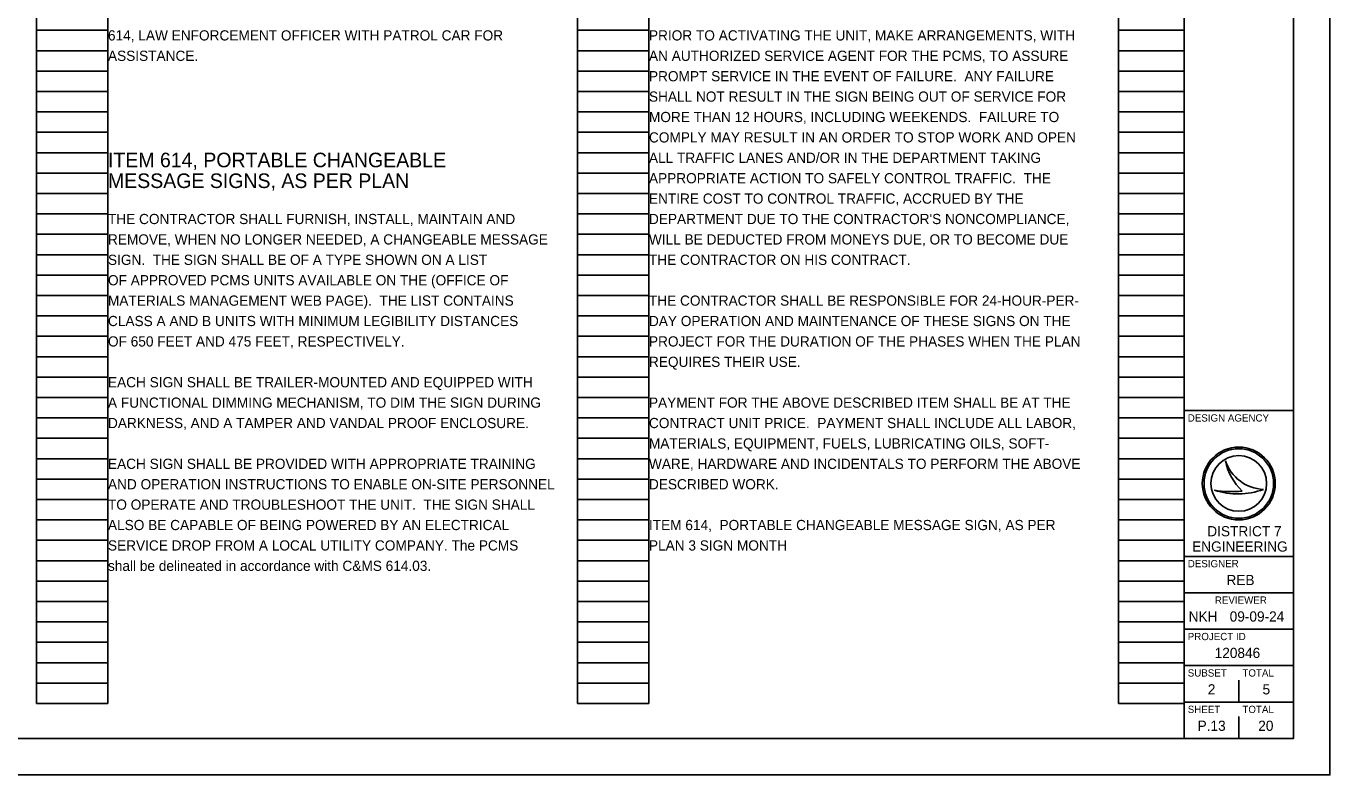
# Model space of a CAD drawing. Extents: x -7.9 to 34, y 0 to 22.
# Drawn here: x 16.12 to 34, y 0 to 10.28 of the extents above; entities that cross this region are included whole.
import ezdxf

# ---------------------------------------------------------------- set-up
doc = ezdxf.new("R2010")
doc.units = 0
for name, color, linetype in [('Default', 7, 'Continuous'), ('SH_Border', 7, 'Continuous'), ('SH_Cut_Line', 7, 'Continuous'), ('SH_Data', 7, 'Continuous'), ('SH_Text', 7, 'Continuous')]:
    doc.layers.add(name, color=color, linetype=linetype)

msp = doc.modelspace()

# ---------------------------------------------------------------- linework, layer by layer
at = {"layer": 'SH_Border'}
for p, q in [((32, 0.5), (32, 21.5)), ((32, 5), (33.5, 5)), ((32, 3), (33.5, 3)), ((32, 2.5), (33.5, 2.5)), ((32, 2), (33.5, 2)), ((32, 1.5), (33.5, 1.5)), ((32, 1), (33.5, 1))]:
    msp.add_line(p, q, dxfattribs=at)
msp.add_lwpolyline([(1.5, 21.5), (33.5, 21.5), (33.5, 0.5), (1.5, 0.5)], close=True, dxfattribs=at)
at = {"layer": 'SH_Cut_Line'}
msp.add_lwpolyline([(0, 0), (34, 0), (34, 22), (0, 22)], close=True, dxfattribs=at)
at = {"layer": 'SH_Data'}
for p, q in [((16.26, 0.98), (16.26, 21.14)), ((17.24, 0.98), (17.24, 21.14)), ((23.68, 0.98), (23.68, 21.14)), ((24.66, 0.98), (24.66, 21.14)), ((31.1, 0.98), (31.1, 21.14)), ((32, 0.98), (32, 21.14)), ((16.26, 10.22), (17.24, 10.22)), ((23.68, 10.22), (24.66, 10.22)), ((31.1, 10.22), (32, 10.22)), ((16.26, 9.94), (17.24, 9.94)), ((23.68, 9.94), (24.66, 9.94)), ((31.1, 9.94), (32, 9.94)), ((16.26, 9.66), (17.24, 9.66)), ((23.68, 9.66), (24.66, 9.66)), ((31.1, 9.66), (32, 9.66)), ((16.26, 9.38), (17.24, 9.38)), ((23.68, 9.38), (24.66, 9.38)), ((31.1, 9.38), (32, 9.38)), ((16.26, 9.1), (17.24, 9.1)), ((23.68, 9.1), (24.66, 9.1)), ((31.1, 9.1), (32, 9.1)), ((16.26, 8.82), (17.24, 8.82)), ((23.68, 8.82), (24.66, 8.82)), ((31.1, 8.82), (32, 8.82)), ((16.26, 8.54), (17.24, 8.54)), ((23.68, 8.54), (24.66, 8.54)), ((31.1, 8.54), (32, 8.54)), ((16.26, 8.26), (17.24, 8.26)), ((23.68, 8.26), (24.66, 8.26)), ((31.1, 8.26), (32, 8.26)), ((16.26, 7.98), (17.24, 7.98)), ((23.68, 7.98), (24.66, 7.98)), ((31.1, 7.98), (32, 7.98)), ((16.26, 7.7), (17.24, 7.7)), ((23.68, 7.7), (24.66, 7.7)), ((31.1, 7.7), (32, 7.7)), ((16.26, 7.42), (17.24, 7.42)), ((23.68, 7.42), (24.66, 7.42)), ((31.1, 7.42), (32, 7.42)), ((16.26, 7.14), (17.24, 7.14)), ((23.68, 7.14), (24.66, 7.14)), ((31.1, 7.14), (32, 7.14)), ((16.26, 6.86), (17.24, 6.86)), ((23.68, 6.86), (24.66, 6.86)), ((31.1, 6.86), (32, 6.86)), ((16.26, 6.58), (17.24, 6.58)), ((23.68, 6.58), (24.66, 6.58)), ((31.1, 6.58), (32, 6.58)), ((16.26, 6.3), (17.24, 6.3)), ((23.68, 6.3), (24.66, 6.3)), ((31.1, 6.3), (32, 6.3)), ((16.26, 6.02), (17.24, 6.02)), ((23.68, 6.02), (24.66, 6.02)), ((31.1, 6.02), (32, 6.02)), ((16.26, 5.74), (17.24, 5.74)), ((23.68, 5.74), (24.66, 5.74)), ((31.1, 5.74), (32, 5.74)), ((16.26, 5.46), (17.24, 5.46)), ((23.68, 5.46), (24.66, 5.46)), ((31.1, 5.46), (32, 5.46)), ((16.26, 5.18), (17.24, 5.18)), ((23.68, 5.18), (24.66, 5.18)), ((31.1, 5.18), (32, 5.18)), ((16.26, 4.9), (17.24, 4.9)), ((23.68, 4.9), (24.66, 4.9)), ((31.1, 4.9), (32, 4.9)), ((16.26, 4.62), (17.24, 4.62)), ((23.68, 4.62), (24.66, 4.62)), ((31.1, 4.62), (32, 4.62)), ((16.26, 4.34), (17.24, 4.34)), ((23.68, 4.34), (24.66, 4.34)), ((31.1, 4.34), (32, 4.34)), ((32.567, 4.31), (32.567, 4.31)), ((16.26, 4.06), (17.24, 4.06)), ((23.68, 4.06), (24.66, 4.06)), ((31.1, 4.06), (32, 4.06)), ((32.75, 4), (32.75, 4)), ((16.26, 3.78), (17.24, 3.78)), ((23.68, 3.78), (24.66, 3.78)), ((31.1, 3.78), (32, 3.78)), ((32.417, 3.91), (32.417, 3.91)), ((33.087, 3.919), (33.087, 3.919)), ((16.26, 3.5), (17.24, 3.5)), ((23.68, 3.5), (24.66, 3.5)), ((31.1, 3.5), (32, 3.5)), ((16.26, 3.22), (17.24, 3.22)), ((23.68, 3.22), (24.66, 3.22)), ((31.1, 3.22), (32, 3.22)), ((16.26, 2.94), (17.24, 2.94)), ((23.68, 2.94), (24.66, 2.94)), ((31.1, 2.94), (32, 2.94)), ((16.26, 2.66), (17.24, 2.66)), ((23.68, 2.66), (24.66, 2.66)), ((31.1, 2.66), (32, 2.66)), ((16.26, 2.38), (17.24, 2.38)), ((23.68, 2.38), (24.66, 2.38)), ((31.1, 2.38), (32, 2.38)), ((16.26, 2.1), (17.24, 2.1)), ((23.68, 2.1), (24.66, 2.1)), ((31.1, 2.1), (32, 2.1)), ((16.26, 1.82), (17.24, 1.82)), ((23.68, 1.82), (24.66, 1.82)), ((31.1, 1.82), (32, 1.82)), ((16.26, 1.54), (17.24, 1.54)), ((23.68, 1.54), (24.66, 1.54)), ((31.1, 1.54), (32, 1.54)), ((16.26, 1.26), (17.24, 1.26)), ((23.68, 1.26), (24.66, 1.26)), ((31.1, 1.26), (32, 1.26)), ((32.75, 1), (32.75, 1.3)), ((16.26, 0.98), (17.24, 0.98)), ((23.68, 0.98), (24.66, 0.98)), ((31.1, 0.98), (32, 0.98)), ((32.75, 0.5), (32.75, 0.8)), ((32.375, 0.675), (32.375, 0.675))]:
    msp.add_line(p, q, dxfattribs=at)
for radius in [0.5, 0.477, 0.477, 0.382]:
    msp.add_circle((32.75, 4), radius, dxfattribs=at)
for centre, radius, start, end in [((33.116, 4.498), 0.58, 198.9257, 198.9319), ((33.347, 4.47), 0.796, 191.6379, 191.6421), ((33.116, 4.498), 0.58, 198.9319, 267.1657), ((33.347, 4.47), 0.796, 191.6421, 226.0947), ((32.739, 4.87), 1.013, 251.4576, 290.0832), ((32.648, 5.154), 1.266, 259.4964, 259.4995), ((32.739, 4.87), 1.013, 251.4527, 251.4576), ((32.648, 5.154), 1.266, 259.4995, 276.6672)]:
    msp.add_arc(centre, radius, start, end, dxfattribs=at)

# ---------------------------------------------------------------- texts
at = {"layer": 'Default'}
for s, height, p in [('ITEM 614, PORTABLE CHANGEABLE ', 0.2, (17.24, 8.34)), ('MESSAGE SIGNS, AS PER PLAN', 0.2, (17.24, 8.055)), ('120846', 0.14, (32.419, 1.605))]:
    msp.add_text(s, height=height, dxfattribs=at).set_placement(p)
at = {"layer": 'SH_Data'}
for s, height, p in [('DESIGN AGENCY', 0.1, (32.05, 4.85)), ('DESIGNER', 0.1, (32.05, 2.85)), ('REB', 0.14, (32.581, 2.605)), ('REVIEWER', 0.1, (32.422, 2.35)), ('NKH', 0.14, (32.062, 2.105)), ('09-09-24', 0.14, (32.625, 2.105)), ('PROJECT ID', 0.1, (32.05, 1.85)), ('SUBSET', 0.1, (32.05, 1.35)), ('TOTAL', 0.1, (32.8, 1.35)), ('2', 0.14, (32.325, 1.105)), ('5', 0.14, (33.076, 1.105)), ('SHEET', 0.1, (32.05, 0.85)), ('TOTAL', 0.1, (32.8, 0.85)), ('P.13', 0.14, (32.185, 0.605)), ('20', 0.14, (33.017, 0.605))]:
    msp.add_text(s, height=height, dxfattribs=at).set_placement(p)
at = {"layer": 'SH_Text'}
for s, p in [('614, LAW ENFORCEMENT OFFICER WITH PATROL CAR FOR', (17.24, 10.08)), ('PRIOR TO ACTIVATING THE UNIT, MAKE ARRANGEMENTS, WITH ', (24.66, 10.08)), ('ASSISTANCE.', (17.24, 9.8)), ('AN AUTHORIZED SERVICE AGENT FOR THE PCMS, TO ASSURE', (24.66, 9.8)), ('PROMPT SERVICE IN THE EVENT OF FAILURE.  ANY FAILURE', (24.66, 9.52)), ('SHALL NOT RESULT IN THE SIGN BEING OUT OF SERVICE FOR', (24.66, 9.24)), ('MORE THAN 12 HOURS, INCLUDING WEEKENDS.  FAILURE TO', (24.66, 8.96)), ('COMPLY MAY RESULT IN AN ORDER TO STOP WORK AND OPEN', (24.66, 8.68)), ('ALL TRAFFIC LANES AND/OR IN THE DEPARTMENT TAKING', (24.66, 8.4)), ('APPROPRIATE ACTION TO SAFELY CONTROL TRAFFIC.  THE', (24.66, 8.12)), ('ENTIRE COST TO CONTROL TRAFFIC, ACCRUED BY THE', (24.66, 7.84)), ('THE CONTRACTOR SHALL FURNISH, INSTALL, MAINTAIN AND', (17.24, 7.56)), ("DEPARTMENT DUE TO THE CONTRACTOR'S NONCOMPLIANCE,", (24.66, 7.56)), ('REMOVE, WHEN NO LONGER NEEDED, A CHANGEABLE MESSAGE', (17.24, 7.28)), ('WILL BE DEDUCTED FROM MONEYS DUE, OR TO BECOME DUE', (24.66, 7.28)), ('SIGN.  THE SIGN SHALL BE OF A TYPE SHOWN ON A LIST', (17.24, 7)), ('THE CONTRACTOR ON HIS CONTRACT.', (24.66, 7)), ('OF APPROVED PCMS UNITS AVAILABLE ON THE (OFFICE OF', (17.24, 6.72)), ('MATERIALS MANAGEMENT WEB PAGE).  THE LIST CONTAINS', (17.24, 6.44)), ('THE CONTRACTOR SHALL BE RESPONSIBLE FOR 24-HOUR-PER-', (24.66, 6.44)), ('CLASS A AND B UNITS WITH MINIMUM LEGIBILITY DISTANCES', (17.24, 6.16)), ('DAY OPERATION AND MAINTENANCE OF THESE SIGNS ON THE', (24.66, 6.16)), ('OF 650 FEET AND 475 FEET, RESPECTIVELY.', (17.24, 5.88)), ('PROJECT FOR THE DURATION OF THE PHASES WHEN THE PLAN', (24.66, 5.88)), ('REQUIRES THEIR USE.', (24.66, 5.6)), ('EACH SIGN SHALL BE TRAILER-MOUNTED AND EQUIPPED WITH', (17.24, 5.32)), ('A FUNCTIONAL DIMMING MECHANISM, TO DIM THE SIGN DURING', (17.24, 5.04)), ('PAYMENT FOR THE ABOVE DESCRIBED ITEM SHALL BE AT THE', (24.66, 5.04)), ('DARKNESS, AND A TAMPER AND VANDAL PROOF ENCLOSURE.', (17.24, 4.76)), ('CONTRACT UNIT PRICE.  PAYMENT SHALL INCLUDE ALL LABOR,', (24.66, 4.76)), ('MATERIALS, EQUIPMENT, FUELS, LUBRICATING OILS, SOFT-', (24.66, 4.48)), ('EACH SIGN SHALL BE PROVIDED WITH APPROPRIATE TRAINING', (17.24, 4.2)), ('WARE, HARDWARE AND INCIDENTALS TO PERFORM THE ABOVE', (24.66, 4.2)), ('AND OPERATION INSTRUCTIONS TO ENABLE ON-SITE PERSONNEL', (17.24, 3.92)), ('DESCRIBED WORK.', (24.66, 3.92)), ('TO OPERATE AND TROUBLESHOOT THE UNIT.  THE SIGN SHALL', (17.24, 3.64)), ('ALSO BE CAPABLE OF BEING POWERED BY AN ELECTRICAL', (17.24, 3.36)), ('ITEM 614,  PORTABLE CHANGEABLE MESSAGE SIGN, AS PER', (24.66, 3.36)), ('    DISTRICT 7 ', (32.11, 3.275)), ('SERVICE DROP FROM A LOCAL UTILITY COMPANY. The PCMS', (17.24, 3.08)), ('PLAN 3 SIGN MONTH', (24.66, 3.08)), ('ENGINEERING', (32.11, 3.065)), ('shall be delineated in accordance with C&MS 614.03.', (17.24, 2.8))]:
    msp.add_text(s, height=0.14, dxfattribs=at).set_placement(p)

doc.saveas('drawing.dxf')
